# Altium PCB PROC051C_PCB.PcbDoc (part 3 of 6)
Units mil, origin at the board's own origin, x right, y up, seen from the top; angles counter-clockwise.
Board outline 3304.03 x 2647.77 mil, 6 copper layers (TOP, L2, L3, L4, L5, BOTTOM), stack 55.54 mil thick; 370 components, 273 nets, 1273 pads, 1381 vias.
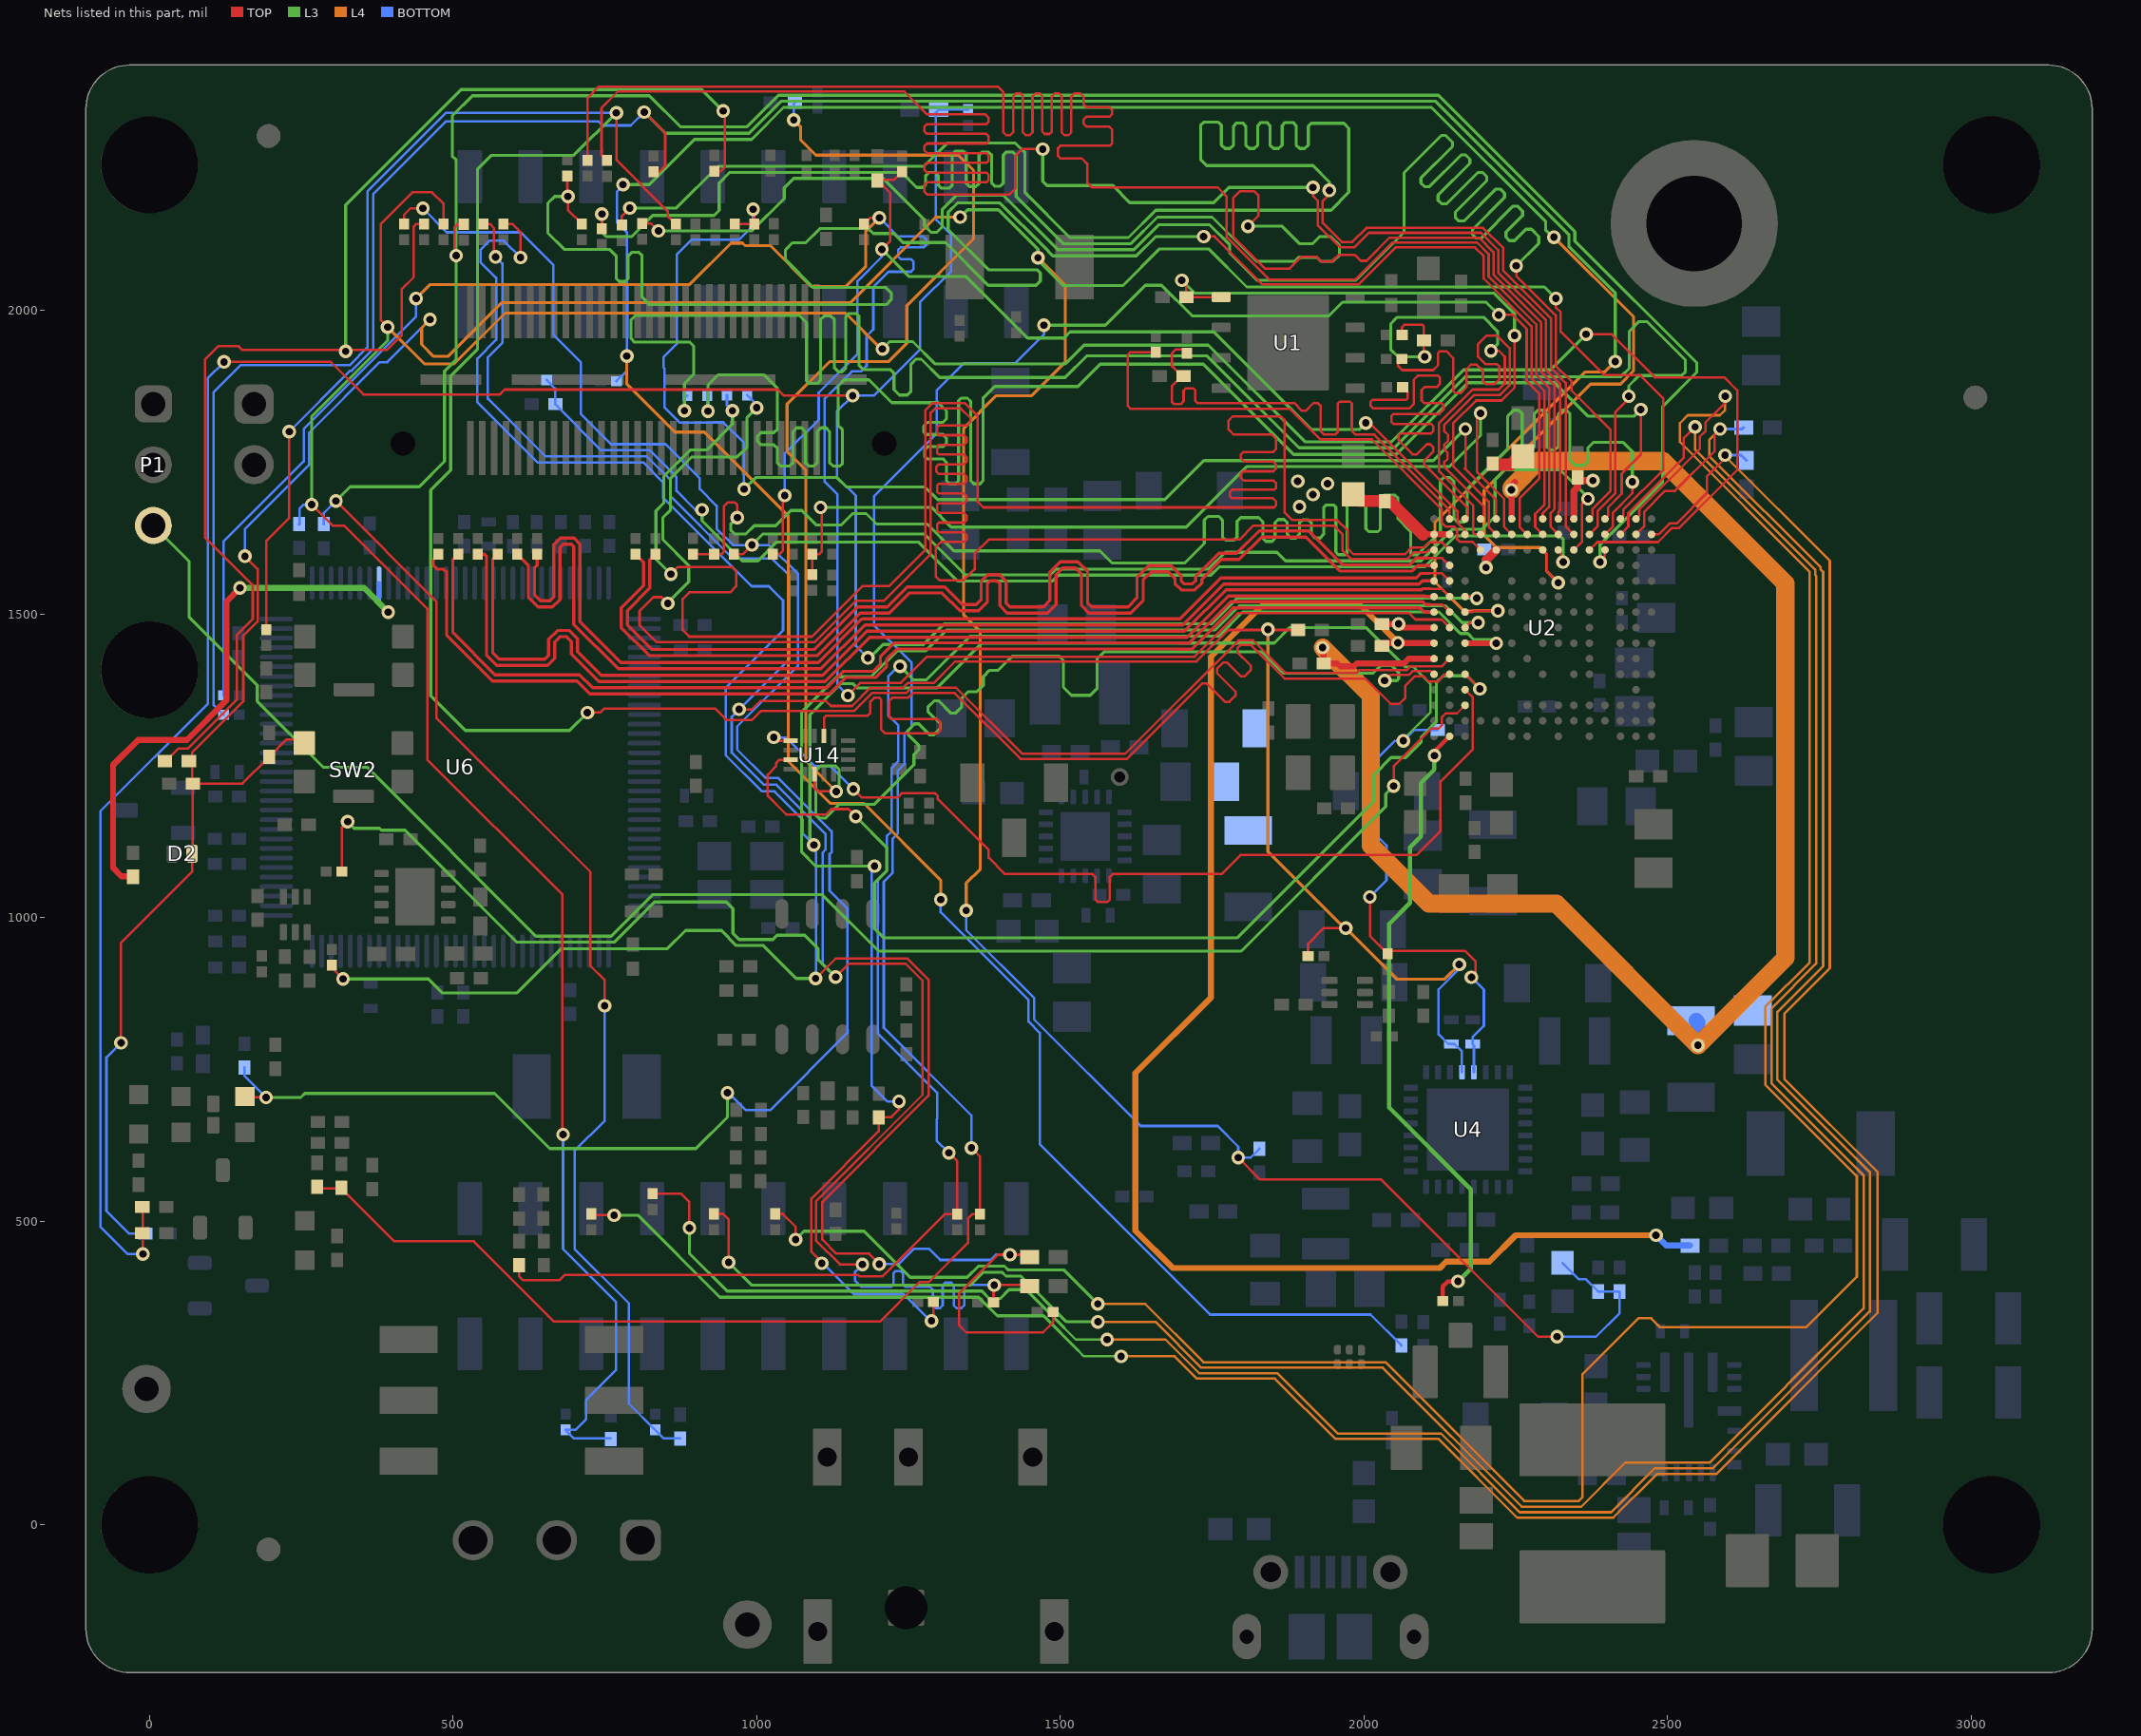
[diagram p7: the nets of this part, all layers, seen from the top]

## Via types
v1: diameter 22.4, hole 12.2, TOP to BOTTOM, tented both sides, 810 vias
v2: diameter 13.77/15.74 (per signal layer), hole 5.9, TOP to L2, tented both sides, 528 vias
v3: diameter 19.68, hole 7.87, TOP to BOTTOM, 23 vias
v4: diameter 19.68, hole 7.87, TOP to BOTTOM, tented both sides, 7 vias
v5: diameter 22.4, hole 12.1, TOP to BOTTOM, tented both sides, 7 vias
v6: diameter 16, hole 8, TOP to BOTTOM, tented both sides, 4 vias
v7: diameter 13.77/15.74 (per signal layer), hole 5.9, TOP to L2, tented top, 1 vias
v8: diameter 22.4/22.4/22.4/22.4/22.4/22.4 (per signal layer), hole 12.2, TOP to BOTTOM, tented both sides, 1 vias

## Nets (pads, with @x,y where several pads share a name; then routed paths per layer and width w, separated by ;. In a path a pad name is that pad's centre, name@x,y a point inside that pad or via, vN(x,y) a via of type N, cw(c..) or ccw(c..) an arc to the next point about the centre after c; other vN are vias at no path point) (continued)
AR_1V24: C3.2 C4.2 C6.2 C7.2 C55.1 C89.2 C101.1 C105.1 L5.2 R146.2 U2.G15 U2.H15 U2.N11 U2.P14 U2.P15 U2.R6 | length 2810.6
  TOP w10: C101.1@2029.68,1448 2033.99,1452.31 2056,1452.31 U2.G15@2115.42,1452.31 ; C4.2@2029.69,1484 v1(2057,1484) 2063.1,1477.9 U2.H15@2115.42,1477.9 ; 2097.06,1631.44 U2.P15@2115.42,1631.44 U2.P14@2141.01,1631.44
  TOP w12: U2.R6@2345.73,1657.03 2345.73,1703 2352,1709.27 C3.2@2352,1725.31 2357.31,1720 v1@2373,1720
  TOP w15: v1(2201,1577) 2201,1589.07 U2.N11@2217.78,1605.85
  TOP w20: C89.2@1993.2,1686.3 C6.2@2034.5,1686.3 ; C6.2@2034.5,1685.91 2042.59,1685.91 2097.06,1631.44
  L4 w10: v1(2056,1453) 1994.63,1514.37 1832.51,1514.37 1747.88,1429.74 1747.88,868.36 1623.8,744.27 1623.8,484.97 1623.54,484.71 1685.25,423 2125.14,423 2135.5,433.37 2206.43,433.37 2250.06,477 v1(2481,477)
  BOTTOM w10: v1(2481,477) 2498,460 R146.2@2537,460
  BOTTOM w20: v1@2200.31,1577.69 v1(2201,1577)
  other v1: 1894,1677 1916,1697 1940,1715 1891,1719 2377,1720
AR_3V3: C5.2 C80.1 C84.2 C87.2 L10.2 U2.F15 U2.R10 | length 2795.5
  TOP w10: v1(1932,1445) 1933.69,1443.31 C84.2@1933.69,1419 1956.22,1419 1961.11,1414.11 1983.23,1414.11 1988.11,1419 2066,1419 2073.72,1426.72 U2.F15@2115.42,1426.72 ; v1(2243,1704.83) 2243,1712.26 v1@2243.37,1712.63 ; U2.R10@2243.37,1657.03 2243.37,1704.83 v1@2243.37,1712.63 ; 2248.74,1718 v1@2243.37,1712.63
  TOP w20: C5.2@2211.95,1748.3 2212.14,1748.11 2213.85,1746.4 2241.8,1746.4 2255.3,1759.9 C87.2@2261.8,1759.9
  L4 w30: v1(1932,1445) 2011.46,1365.54 2011.46,1118.62 2106.95,1023.14 2316.75,1023.14 v1(2550,789.89) 2694,933.89 2694,1550.78 2492.58,1752.2 2287.2,1752.2 2243,1708 v1(2243,1704.83)
  BOTTOM w25: L10.2@2547,830.64 2550,827.64 v1(2550,789.89)
AR_ANAMUX: P1.3 U2.C13 | length 2792.8
  TOP w4: v1@2056.9,1213.47 2053.38,1217 v1(2049,1217) 2049,1249.74 2110.82,1311.56 2122.56,1311.56 2128,1317 2128,1330 2134.66,1336.66 2153.31,1336.66 U2.C13@2166.6,1349.95
  L3 w5: P1.3@6.27,1646.15 65,1587.42 65,1495.2 177.4,1382.8 177.4,1356.45 285.85,1248 358,1248 636.25,969.75 760.31,969.75 828.56,1038 1108.06,1038 1201.06,945 1797.78,945 2036.09,1183.32 2036.09,1204.09 v1(2049,1217)
AR_ANATEST1: R46.1 R104.2 U2.P1 | length 4276.8
  TOP w4: R104.2@727.75,512.27 730.02,510 v1(765,510) ; U2.P1@2473.68,1631.44 2485.69,1631.44 2504.26,1650.01 2515.81,1650.01 2564.89,1699.1 2564.89,1726.58 2594.66,1756.35 v1(2594.66,1761.9)
  L3 w4: 1529.65,286.92 1538.97,277.6 v1(1600.06,277.6)
  L3 w5: v1(765,510) 804.19,510 939.19,375 1365.46,375 1396.16,344.3 1472.27,344.3 1529.65,286.92
  L4 w4: v1(1600.06,277.6) 1688.07,277.6 1724.67,241 1853.51,241 1953.05,141.46 2122.98,141.46 2252.64,11.8 2410.65,11.8 2482.43,83.58 2580.03,83.58 2845.54,349.09 2845.54,581.49 2692.23,734.8 2692.23,842 2767.24,917.01 2767.24,1588.08 2594.66,1760.66 v1(2594.66,1761.9)
  BOTTOM w5: v1(2594.66,1761.9) 2621.34,1761.9 R46.1@2629.9,1753.34
AR_ANATEST2: R94.2 R100.1 U2.P2 | length 4338.2
  TOP w4: R94.2@828.25,545.27 875.73,545.27 889,532 v1(889,489) ; U2.P2@2448.09,1631.44 2461.38,1644.73 2461.38,1668.38 2496,1703 2512.11,1703 2577.46,1768.35 2577.46,1796.03 v1(2586.42,1805)
  L3 w4: 1506.18,324.54 1525.46,305.26 v1(1577.08,305.26)
  L3 w5: v1(889,489) v1(889,489) 889.05,447.26 951.31,385 1370.72,385 1382.72,373 1401.4,373 1415.7,387.3 1443.42,387.3 1506.18,324.54
  L4 w4: v1(1577.08,305.26) 1673.15,305.26 1728.4,250 1857.24,250 1956.77,150.46 2126.71,150.46 2256.37,20.8 2406.92,20.8 2479.57,93.45 2575.08,93.45 2833.12,351.49 2833.12,581.18 2681.1,733.21 2681.1,845 2756.22,920.12 2756.22,1569.54 2752.26,1573.5 2752.26,1577.15 2568.67,1760.73 2568.67,1787.25 v1(2586.42,1805)
  BOTTOM w5: v1@2586.42,1800.26 v1(2586.42,1805) 2622.94,1805 R100.1@2625.38,1807.44
AR_ANATEST3: R105.2 U2.P3 | length 4143.4
  TOP w4: R105.2@929.75,512.27 944.73,512.27 953.8,503.2 v1(953.8,432.4) ; U2.P3@2422.5,1631.44 2435.45,1644.39 2435.45,1666.45 2526.85,1757.85 2526.85,1790.1 v1(2545.22,1808.48)
  L3 w5: v1(953.8,432.4) 991.2,395 1352,395 1373.16,416.16 1403.84,416.16 1410.26,409.74 1435.12,409.74 1510.39,334.46 v1(1561.94,334.46)
  L4 w4: v1(1561.94,334.46) 1656.67,334.46 1732.13,259 2030.9,259 2260.1,29.8 2357.65,29.8 2430.3,102.45 2569.05,102.45 2822.84,356.24 2822.84,575.93 2671.04,727.73 2671.04,850.58 2744.82,924.36 2744.82,1563.04 2743.26,1564.6 2743.26,1573.42 2545.22,1771.46 v1(2545.22,1808.48)
AR_ANATEST4: R106.2 U2.R2 | length 4256.2
  TOP w4: R106.2@1030.25,512.27 1042.73,512.27 1064,491 v1(1064,470) ; U2.R2@2448.09,1657.03 2453.38,1662.32 2453.38,1672.38 2553.22,1772.22 2553.22,1792.16 2562.42,1801.36 2562.42,1815.6 2595,1848.18 v1(2595,1859)
  L3 w5: v1(1064,470) 1077.7,483.7 1176.44,483.7 1252.34,407.8 1346.8,407.8 1365.16,426.16 1407.98,426.16 1414.4,419.74 1506.1,419.74 v1(1561.84,364)
  L4 w4: v1(1561.84,364) 1639.86,364 1735.86,268 2035.33,268 2264.03,39.3 2353.71,39.3 2359.69,45.27 2359.69,247.95 2452.01,340.27 2473.04,340.27 2487.42,325.89 2728.8,325.89 2811.82,408.91 2811.82,574.23 2660.97,725.08 2660.97,853.24 2734.26,926.53 2734.26,1569.69 2520.35,1783.6 2520.35,1814.53 2533.5,1827.68 2586.1,1827.68 2595,1836.58 v1(2595,1859)
AR_BSS_LOGGER: R31.1 R135.1 U2.H14 | length 3794.9
  TOP w4: v1(1150,1366) 1171,1387 1237.4,1387 1280.4,1430 1721,1430 1793,1502 2074,1502 2084.81,1491.19 2127.72,1491.19 U2.H14@2141.01,1477.9 ; R31.1@1176.75,2142.71 1187.04,2153 v1(1202,2153)
  L4 w5: v1(439,2020) 462,2043 889.6,2043 958.05,2111.45 976.26,2111.45 980.71,2107 1022.36,2107 1089.36,2040 1147,2040 1179.3,2072.3 1179.3,2130.3 v1(1202,2153)
  BOTTOM w4: R135.1@121.79,1366.19 121.79,1619.69 253.86,1751.76 253.86,1805.3 439,1990.44 v1(439,2020) ; v1(1150,1366) 1133,1383 1133,1697.12 1112,1718.12 1112,1855.3 1156.7,1900 1172,1900 1181,1909 1181,1958 1192,1969 1192,2039 1217,2064 1254,2064 1258,2068 1258,2081 1254,2085 1237,2085 1233,2089 1233,2100 1237,2104 1275,2104 1279,2108 1279,2117.3 1274,2122.3 1232.7,2122.3 v1(1202,2153)
AR_CS1: R14.1 U2.E15 U14.10 | length 3311.4
  TOP w4: U14.10@1095.13,1236.5 1095.13,1213.87 1101,1208 v1(1131,1208) ; v1(2034.18,1390.7) 2043.48,1400 2073.87,1400 2079.87,1406 2110.54,1406 U2.E15@2115.42,1401.13
  L3 w5: v1(1131,1208) 1135.58,1212.58 1135.58,1244.42 1130,1250 1105,1250 1097.5,1242.5 1097.5,1169.5 1103,1164 1113,1164 1136,1187 1194,1187 1259,1252 1259,1268.91 1259.6,1269.51 1266.94,1276.85 1266.94,1283.92 1249.21,1301.65 1249.21,1308.73 1259.82,1319.33 1266.89,1319.33 1284.62,1301.6 1291.69,1301.6 1302.3,1312.21 1302.3,1319.28 1281.8,1339.78 1281.8,1346.85 1292.4,1357.46 1299.47,1357.46 1319.98,1336.95 1327.05,1336.95 1337.65,1347.56 1337.65,1354.63 1337.65,1361.7 1348.26,1372.31 1355.33,1372.31 1362.4,1372.31 1373.01,1382.92 1373.01,1389.99 1373.01,1397.06 1383.62,1407.67 1390.69,1407.67 1397.76,1407.67 1411.9,1421.81 1420.74,1430.65 1498.21,1430.65 1505,1423.86 1505,1379.86 1518.36,1366.5 1549.21,1366.5 1560.71,1378 1560.71,1427 1571.58,1437.88 1832.12,1437.88 1867.2,1402.8 2014.8,1402.8 2027.2,1415.2 2045.95,1415.2 2057.2,1403.95 2057.2,1393.45 2054.45,1390.7 v1(2034.18,1390.7)
  L4 w5: v1(1061,2314) 1072.44,2302.56 1072.44,2280.78 1097.22,2256 1332,2256 1357.16,2230.84 1357.16,2118.16 1247,2008 1247,1946.29 1216.66,1915.95 1119.95,1915.95 1050,1846 1050,1768 1081,1737 1081,1258 v1(1131,1208)
  BOTTOM w4: v1(1061,2314) 1061,2341.02 R14.1@1062.59,2342.6
AR_DMM_CLK: R54.1 U2.N15 | length 3198.6
  TOP w4: v1(853.5,1517.8) 843.3,1528 830,1528 807,1505 807,1482 835,1454 1095,1454 1163,1522 1209.31,1522 1286.62,1599.3 1286.62,1831.62 1294,1839 1336,1839 1352.04,1822.96 1352.04,1817 1345.88,1810.84 1299.73,1810.84 1296.9,1808.01 1296.9,1797.67 1299.73,1794.84 1341.35,1794.84 1346.04,1790.15 1346.04,1783.53 1341.35,1778.84 1299.73,1778.84 1296.9,1776.01 1296.9,1765.67 1299.73,1762.84 1341.35,1762.84 1346.04,1758.15 1346.04,1751.53 1341.35,1746.84 1299.73,1746.84 1295.9,1743.01 1295.9,1734.66 1299.73,1730.84 1341.35,1730.84 1346.04,1726.15 1346.04,1719.53 1341.35,1714.84 1299.73,1714.84 1296.9,1712.01 1296.9,1701.67 1299.73,1698.84 1341.35,1698.84 1346.04,1694.15 1346.04,1687.53 1341.35,1682.84 1299.73,1682.84 1297.24,1680.35 1297.24,1669.33 1299.73,1666.84 1341.35,1666.84 1346.04,1662.15 1346.04,1655.53 1341.35,1650.84 1299.73,1650.84 1296.9,1648.01 1296.9,1637.67 1299.73,1634.84 1341.35,1634.84 1346.04,1630.15 1346.04,1623.53 1341.35,1618.84 1303.16,1618.84 1294.81,1610.49 1294.81,1562.19 1301,1556 1341,1556 1359,1574 1359,1599.7 1382.3,1623 1795,1623 1818,1646 1950,1646 1965,1631 1965,1605 1979.2,1590.8 2070.96,1590.8 2082.16,1602 2103,1602 2106.85,1605.85 U2.N15@2115.42,1605.85
  L3 w5: v1(853.5,1517.8) 853.5,1518.68 888,1553.18 888,1580.1 845.3,1622.8 845.3,1659.2 858,1671.9 858,1724 893,1759 968.02,1759 984.02,1775.03 983.98,1823.96 v1(1000,1840)
  BOTTOM w4: R54.1@984,1861.01 1000,1845.01 v1(1000,1840)
AR_DMM_SYNC: R55.1 U2.N14 | length 3238.5
  TOP w4: v1(858.6,1566) 870.6,1578 959,1578 966.1,1570.9 966.1,1545.74 956.36,1536 889,1536 878,1525 878,1474 889,1463 1091,1463 1174.1,1546.1 1218.1,1546.1 1277.55,1605.55 1277.55,1835.55 1290,1848 1342,1848 1364.01,1825.99 1364.01,1684.99 1373.11,1675.89 1851.89,1675.89 1855.2,1679.2 1855.2,1685.8 1850,1691 1783,1691 1779,1695 1779,1701 1783,1705 1852.31,1705 1855.2,1707.89 1855.2,1715.8 1851,1720 1801.99,1720 1797.5,1724.49 1797.5,1731.11 1801.79,1735.4 1850.71,1735.4 1855.2,1739.89 1855.2,1746.51 1850.31,1751.4 1802.59,1751.4 1797.5,1756.49 1797.5,1763.11 1801.79,1767.4 1850.71,1767.4 1855.2,1771.89 1855.2,1788.8 1848,1796 1785,1796 1777,1804 1777,1819 1784,1826 1863,1826 1869,1820 1869,1668 1882,1655 1956,1655 1973,1638 1973,1608.31 1982.51,1598.8 2067.65,1598.8 2078.85,1610 2099,1610 2107.15,1618.15 2128.71,1618.15 U2.N14@2141.01,1605.85
  L3 w5: v1(858.6,1566) 834,1590.6 834,1670.3 846.9,1683.2 846.9,1727.2 890.2,1770.5 917.4,1770.5 960,1813.1 v1(960,1835)
  BOTTOM w4: R55.1@951,1860.81 951,1844 v1(960,1835)
AR_DP0: R56.1 U2.R4 | length 3201.8
  TOP w4: U2.R4@2396.91,1657.03 2402.2,1662.32 2402.2,1676.2 2424.48,1698.48 2424.48,1731.48 2456,1763 v1(2456,1837)
  L3 w5: v1(919.7,1834.5) 919.7,1877.6 936.1,1894 1012.1,1894 1034,1872.1 1034,1804.87 1028.14,1799.01 1006.86,1799.01 1001,1793.15 1001,1784.87 1006.86,1779.01 1028.14,1779.01 1034,1773.15 1034,1749.01 1039.01,1744 1053.99,1744 1059.85,1749.86 1059.85,1801.14 1065.71,1807 1073.99,1807 1079.85,1801.14 1079.85,1749.86 1085.71,1744 1093.99,1744 1099.85,1749.86 1099.85,1801.14 1105.71,1807 1113.99,1807 1119.85,1801.14 1119.85,1749.86 1125.71,1744 1137,1744 1141.32,1748.32 1141.32,1803.58 1134,1810.9 1134,1875.4 1144.6,1886 1185,1886 1222.46,1848.54 1298.8,1848.54 1312.54,1834.8 1312.54,1821.77 1306.68,1815.91 1281.11,1815.91 1275.12,1809.91 1275.12,1799.54 1278.75,1795.91 1306.68,1795.91 1312.54,1790.05 1312.54,1781.77 1306.68,1775.91 1281.66,1775.91 1276.79,1771.05 1276.79,1758.97 1279.85,1755.91 1306.68,1755.91 1312.54,1750.05 1312.54,1719.73 1317.54,1714.73 1327.54,1714.73 1332.54,1719.73 1332.54,1851.68 1336.67,1855.81 1346.99,1855.81 1352.54,1850.26 1352.54,1719.73 1357.54,1714.73 1367.54,1714.73 1372.54,1719.73 1372.54,1855.54 1392,1875 1529,1875 1565.7,1911.7 1735.5,1911.7 1884.2,1763 2053,1763 2171.26,1881.26 2313.74,1881.26 2368.7,1826.3 2445.3,1826.3 v1(2456,1837)
  BOTTOM w4: R56.1@918.5,1860.31 919.7,1859.11 v1(919.7,1834.5)
AR_DP1: R57.1 U2.P5 | length 3202.6
  TOP w4: U2.P5@2371.32,1631.44 2384.61,1644.73 2384.61,1669.97 2414,1699.36 2414,1833 2436.17,1855.17 v1(2436.17,1859)
  L3 w5: v1(881,1835) 881,1880 896,1895 896,1942 889.9,1948.1 798.9,1948.1 793,1954 793,1985 800.1,1992.1 1070.21,1992.1 1082,1980.31 1082,1884 1086,1880 1100,1880 1104.97,1884.97 1104.97,1985.26 1110.79,1991.08 1122.19,1991.08 1127.99,1985.28 1127.99,1905.44 1134.43,1899 1140.56,1899 1146.69,1905.13 1146.69,1990.69 1151,1995 1164,1995 1168.7,1990.3 1168.7,1909.3 1175,1903 1220,1903 1226,1897 1226,1870 1235,1861 1248,1861 1254,1867 1254,1912 1262,1920 1271,1920 1301,1890 1508,1890 1543.4,1925.4 1741.7,1925.4 1893.1,1774 2049.86,1774 2167.12,1891.26 2423.26,1891.26 2437,1905 2437,1966 2453,1982 2465.91,1982 2529.5,1918.41 2529.5,1899.5 2523,1893 2453,1893 2436.17,1876.17 v1(2436.17,1859)
  BOTTOM w4: v1(881,1835) 881,1855.11 880.7,1855.41 R57.1@885.6,1860.31
AR_DP2: R179.1 U2.R5 | length 3203.3
  TOP w4: R179.1@811,2143.49 826.01,2143.49 v1(838.1,2131.4) ; v1(2250.8,2073.7) 2250.8,2057.2 2316,1992 2316,1909 2342,1883 2342,1868 2405.89,1804.11 2405.89,1702.57 2376.61,1673.29 2376.61,1662.32 U2.R5@2371.32,1657.03
  L3 w5: v1(838.1,2131.4) 992.2,2131.4 1045.3,2184.5 1045.3,2202.16 1060.84,2217.7 1208.3,2217.7 1276,2150 1276,2140 1287,2129 1296.74,2129 1305.3,2137.56 1305.3,2166.3 1328.8,2189.8 1406.4,2189.8 1495.9,2100.3 1621.16,2100.3 1662.56,2141.7 1745.3,2141.7 1779,2108 1779,2095 1824,2050 1987,2050 2066,2129 2066,2227 2127.66,2288.66 2134.74,2288.66 2145.89,2277.51 2145.89,2270.43 2093.87,2218.41 2093.87,2210.13 2099.74,2204.26 2108.02,2204.26 2160.34,2256.58 2167.42,2256.58 2174.49,2249.51 2174.49,2242.43 2122.17,2190.11 2122.17,2181.83 2128.04,2175.96 2136.32,2175.96 2188.14,2227.78 2195.22,2227.78 2202.29,2220.71 2202.29,2213.63 2150.47,2161.81 2150.47,2153.53 2156.34,2147.66 2164.62,2147.66 2217.29,2200.33 2224.37,2200.33 2231.44,2193.26 2231.44,2186.18 2178.77,2133.51 2178.77,2125.23 2184.64,2119.36 2192.92,2119.36 2245.79,2172.23 2252.87,2172.23 2261.17,2163.93 2261.17,2156.85 2233.8,2129.48 2233.8,2121.2 2239.67,2115.33 2247.95,2115.33 2266.62,2134 2276,2134 2288,2122 2288,2110.9 v1(2250.8,2073.7)
AR_DP3: R180.1 U2.P6 | length 3247.7
  TOP w4: R180.1@777.7,2143.69 777.7,2155.7 v1(791,2169) ; v1(1943,2198) 1943,2191.31 1932,2180.31 1932,2144.31 1963.31,2113 1981,2113 2004.2,2136.2 2196.13,2136.2 2229.35,2102.98 2229.35,2065.91 2308,1987.25 2308,1905.69 2332.44,1881.25 2332.44,1644.73 U2.P6@2345.73,1631.44
  L3 w5: v1(791,2169) 867.5,2169 936.2,2237.7 1275.3,2237.7 1313.6,2276 1426,2276 1441.7,2260.3 1441.7,2194.1 1515.5,2120.3 1612.16,2120.3 1657.35,2165.49 1945.69,2165.49 1975,2194.8 1975,2300.4 1966.8,2308.6 1913.32,2308.6 1908.32,2303.6 1908.32,2272.86 1902.46,2267 1894.18,2267 1888.32,2272.86 1888.32,2304.9 1883.32,2309.9 1870.27,2309.9 1865.27,2304.9 1865.27,2272.86 1859.41,2267 1851.13,2267 1845.27,2272.86 1845.27,2304.9 1840.27,2309.9 1830.27,2309.9 1825.27,2304.9 1825.27,2272.86 1819.41,2267 1811.13,2267 1805.27,2272.86 1805.27,2304.1 1800.27,2309.1 1790.27,2309.1 1785.27,2304.1 1785.27,2272.86 1779.41,2267 1771.13,2267 1765.27,2272.86 1765.27,2305.4 1760.27,2310.4 1736,2310.4 1731,2305.4 1731,2249 1741,2239 1916,2239 1943,2212 v1(1943,2198)
AR_DP4: R181.1 U2.R7 | length 3253.6
  TOP w4: R181.1@753.5,2247.29 744.4,2256.39 744.4,2334 771.4,2361 1243,2361 1280.69,2323.31 1376.31,2323.31 1382,2317.62 1382,2311.31 1378,2307.31 1280.69,2307.31 1276,2302.62 1276,2296 1280.69,2291.31 1377.99,2291.31 1382,2287.3 1382,2279.31 1378,2275.31 1280.69,2275.31 1276,2270.62 1276,2264 1280.69,2259.31 1377.99,2259.31 1382,2255.3 1382,2247.31 1378,2243.31 1280.69,2243.31 1276,2238.62 1276,2232 1280.69,2227.31 1377.99,2227.31 1382,2223.3 1382,2215.31 1378,2211.31 1280.69,2211.31 1276,2206.62 1276,2196 1281,2191 1416,2191 1426,2201 1426,2255 1437,2266 v1(1471,2266) ; v1(1916,2203) 1916,2189 1924,2181 1924,2141 1961,2104 1984,2104 2008.2,2128.2 2192.81,2128.2 2221.35,2099.67 2221.35,2062.59 2300,1983.94 2300,1902.37 2323,1879.37 2323,1670.86 2320.14,1668 U2.R7@2320.14,1657.03
  L3 w5: v1(1471,2266) 1471,2213 1478,2206 1586.46,2206 1614.46,2178 1752.7,2178 1777.7,2203 v1(1916,2203)
AR_DP5: R182.1 U2.P7 | length 3177.1
  TOP w4: R182.1@745,2137.99 v1(745,2159) ; v1(1809,2139) 1826,2156 1826,2190 1819,2197 1796,2197 1785,2186 1785,2121.5 1837.5,2069 1877,2069 1897,2089 1921,2089 1929,2081 1948,2081 1959,2092 1985,2092 1995,2082 2004,2082 2042.2,2120.2 2189.5,2120.2 2213.35,2096.35 2213.35,2059.28 2292,1980.63 2292,1899 2314,1877 2314,1673.17 2307.6,1666.77 2307.6,1643.98 U2.P7@2320.14,1631.44
  L3 w5: v1(745,2159) 745,2129 752,2122 794,2122 828.8,2156.8 929.8,2156.8 938,2165 938,2210 955.7,2227.7 1238.24,2227.7 1263.14,2202.8 1273.14,2202.8 1278.14,2207.8 1278.14,2222.5 1283.14,2227.5 1294,2227.5 1299,2222.5 1299,2206.6 1304,2201.6 1317,2201.6 1322,2206.6 1322,2257.4 1327,2262.4 1340,2262.4 1345,2257.4 1345,2210 1350.5,2204.5 1361,2204.5 1366,2209.5 1366,2256.3 1371,2261.3 1382,2261.3 1387,2256.3 1387,2210.1 1392,2205.1 1401,2205.1 1406,2210.1 1406,2256 1411,2261 1422,2261 1427,2256 1427,2188 1504.7,2110.3 1616.3,2110.3 1660,2154 1750,2154 1822.66,2081.34 1886.34,2081.34 1893,2088 1922.34,2088 1929,2081.34 1949.05,2081.34 1959.79,2092.09 1959.79,2107.28 1945.07,2122 1927,2122 1915,2110 1894.35,2110 1865.35,2139 v1(1809,2139)
AR_DP6: R183.1 U2.R8 | length 3114.7
  TOP w4: R183.1@721,2247.69 721,2350 740,2369 1397,2369 1406.14,2359.86 1406.14,2293.69 1410.83,2289 1417.45,2289 1422.14,2293.69 1422.14,2352.81 1427.23,2357.9 1433.85,2357.9 1438.14,2353.61 1438.14,2293.69 1442.83,2289 1449.45,2289 1454.14,2293.69 1454.14,2352.81 1459.23,2357.9 1465.85,2357.9 1470.14,2353.61 1470.14,2295 1474.14,2291 1482.14,2291 1486.14,2295 1486.14,2352.81 1491.23,2357.9 1497.85,2357.9 1502.14,2353.61 1502.14,2293.69 1506.83,2289 1513.45,2289 1518.14,2293.69 1518.14,2352.81 1523.23,2357.9 1532.6,2357.9 1538,2352.5 1538,2340.1 1542.69,2335.41 1580.01,2335.41 1585.2,2330.22 1585.2,2323.6 1581.01,2319.41 1542.69,2319.41 1538,2314.72 1538,2308.1 1542.69,2303.41 1580.01,2303.41 1585.2,2298.22 1585.2,2275.2 1581.66,2271.66 1500.05,2271.66 1496.1,2267.71 1496.1,2254.73 1499.92,2250.91 1535.09,2250.91 1544.2,2241.8 1544.2,2210.8 1551.9,2203.1 1758.9,2203.1 1774,2188 1774,2121.19 1843.96,2051.23 1986.23,2051.23 2047.2,2112.2 2186.19,2112.2 2205.35,2093.04 2205.35,2055.97 2284,1977.31 2284,1894 2305,1873 2305,1676.69 2294.55,1666.24 U2.R8@2294.55,1657.03
AR_DP7: R60.2 R184.1 U2.P8 | length 3352.6
  TOP w4: R60.2@688,2222.01 688,2189 v1(689,2188) 689,2165.99 R184.1@712,2142.99 ; v1(1736,2122) 1754,2122 1832.77,2043.23 1991.23,2043.23 2052.2,2104.2 2182.87,2104.2 2197.35,2089.73 2197.35,2052.65 2276,1974 2276,1889 2297,1868 2297,1680 2282.05,1665.05 2282.05,1643.94 U2.P8@2294.55,1631.44
  L3 w5: v1(689,2188) 667,2188 656,2177 656,2128 683,2101 757.54,2101 768.4,2090.14 768.4,2053.1 773.4,2048.1 783.4,2048.1 788.4,2053.1 788.4,2090.14 794.26,2096 806,2096 811,2091 811,2022 823.1,2009.9 1213.3,2009.9 1221.6,2018.2 1221.6,2029.1 1212.7,2038 1093.14,2038 1047.3,2083.84 1047.3,2100.16 1058.84,2111.7 1080.7,2111.7 1104,2135 1184,2135 1192,2127 1226,2127 1240.9,2112.1 1310.9,2112.1 1381.2,2041.8 1460.3,2041.8 1467.1,2048.6 1467.1,2061.9 1461.7,2067.3 1381.7,2067.3 1315.3,2133.7 1315.3,2162.16 1330.54,2177.4 1400.74,2177.4 1473,2105.14 1473,2105 1487.7,2090.3 1625.3,2090.3 1657,2122 v1(1736,2122)
AR_GPIO_0: R164.1 R178.2 U2.H13 | length 2610.4
  TOP w4: v1(1107,431) 1107,433 1090,450 1090,537.32 1200.8,648.12 R178.2@1200.8,670.91 1200.8,671.7 1221.7,671.7 1234.2,684.2 v1(1234.2,697.5) ; v1(1288,336) 1290.99,338.99 R164.1@1290.99,367 ; U2.H13@2166.6,1477.9 2174.7,1486 2183,1486 2185.5,1483.5 v1@2188,1481 ; v1(2188,1486) v1@2188,1481 ; v1@2190,1479 v1@2188,1481
  L3 w5: v1(1194,1085) 1097.3,1085 1074,1108.3 1074,1339 1132,1397 1188.14,1397 1230.52,1439.38 1277.97,1439.38 1312.59,1474 1754.86,1474 1794.56,1513.7 2134.3,1513.7 2162,1486 v1(2188,1486)
  BOTTOM w4: v1(1107,431) 1109,431 1160,380 1242,380 1286,336 v1(1288,336) ; v1(1194,1085) 1189.2,1080.2 1189.2,723.2 1214.9,697.5 v1(1234.2,697.5)
AR_GPIO_1: R9.2 R72.2 U2.J13 | length 4001.2
  TOP w4: R72.2@192.5,1474.24 192.5,1620.81 230.02,1658.33 v1(230.02,1800.7) ; v1(814.6,2327.1) 849.2,2292.5 849.2,2238.2 839.73,2228.73 R9.2@829.75,2228.73 ; U2.J13@2166.6,1503.49 2178.49,1503.49 2180.45,1505.45 v1(2220.59,1505.45)
  L3 w5: v1(814.6,2327.1) 849.7,2292 987.2,2292 1039.94,2344.74 2118.36,2344.74 2337.4,2125.7 2337.4,2105.8 2414,2029.19 v1(2414,1916)
  L4 w5: v1(2220.59,1505.45) 2220.34,1505.7 2179.84,1505.7 2179.59,1505.45 2164.55,1505.45 2117,1553 2117,1651.14 2364.86,1899 2397,1899 v1(2414,1916)
  BOTTOM w4: v1(230.02,1800.7) 330.32,1901 333,1901 368.21,1936.21 368.21,2191.71 488.5,2312 739.03,2312 746.02,2305.01 792.51,2305.01 v1(814.6,2327.1)
AR_GPIO_2: R8.2 R110.2 R116.1 R147.1 U2.K13 | length 4887.2
  TOP w4: R110.2@-11.18,523.77 -11,523.59 -11,480.33 v1(-11,446) ; v1(122.7,1915.5) 298.7,1915.5 352.2,1862 577,1862 585,1870 1035,1870 1045,1860 v1(1158,1860) ; U2.K13@2166.6,1529.08 2182.87,1529.08 v1(2185.75,1526.2)
  L3 w5: v1(1183,1428) 1186,1428 1208,1450 1274.44,1450 1308.44,1484 1749,1484 1791.2,1526.2 v1(2185.75,1526.2)
  BOTTOM w4: v1(-11,446) -36,446 -81,491 -81,1175.47 95.73,1352.21 95.73,1888.53 v1(122.7,1915.5) ; v1(1183,1428) 1163,1448 1163,1695.4 1132,1726.4 1132,1834 v1(1158,1860) 1193,1860 1269,1936 1269,2014 1320,2065 1320,2125 1295,2150 1295,2326.38 R147.1@1299.62,2331 R8.2@1348,2330.99
AR_HOSTINTR1: R10.2 R13.2 R64.2 U2.P13 | length 1945.7
  TOP w4: R64.2@1026.61,1598.73 1037.03,1598.73 1043,1604.7 1043,1692.5 v1(1046,1695.5) ; v1(1206,2101) 1220,2115 1220,2193.55 1198.79,2214.76 1198.4,2215.15 1225.67,2215.15 R10.2@1239.25,2228.73 ; v1(2003,1815) 2008.81,1815 2153.85,1669.96 2153.85,1650.79 2166.6,1638.04 U2.P13@2166.6,1631.44
  L3 w5: v1(1206,2101) 1251,2056 1336.8,2056 1336.9,2056.1 1345.1,2056.1 1446.2,1955 1506,1955 1516,1965 1752.8,1965 1913.8,1804 1992,1804 v1(2003,1815)
  BOTTOM w4: v1(1046,1695.5) 1046,1764 1102,1820 1102,1864.86 1166,1928.86 1166,2048.7 1206,2088.7 v1(1206,2101)
AR_LVDS_0_N: R48.2 U2.J15 | length 1887.4
  TOP w5.2: R48.2@475.61,1598.73 467.4,1590.52 467.4,1580.4 473.7,1574.1 484.1,1574.1 489.3,1568.9 489.3,1465.28 564.58,1390 703.96,1390 725.16,1368.8 725.33,1368.63 1119.94,1368.63 1147.13,1395.82 1196.32,1395.82 1213.8,1413.31 1213.8,1425.8 1230.6,1442.6 1691.54,1442.6 1691.74,1442.4 1716.26,1442.4 1716.86,1443 1717.3,1443 1784.9,1510.6 2092.48,1510.6 2099.59,1503.49 U2.J15@2115.42,1503.49
AR_LVDS_0_P: R49.2 U2.J14 | length 1888.2
  TOP w4: 2108,1515.99 2128.51,1515.99 U2.J14@2141.01,1503.49
  TOP w5.2: R49.2@508.25,1598.73 499.5,1589.98 499.5,1469.5 568.8,1400.2 708.19,1400.2 729.56,1378.83 1115.71,1378.83 1142.9,1406.02 1192.09,1406.02 1203.6,1417.53 1203.6,1430.02 1206.59,1433.01 ; 1204.6,1431.02 1206.59,1433.01 ; 2108,1515.99 2101.51,1515.99 2096.7,1520.8 1780.67,1520.8 1713.07,1453.2 1712.64,1453.2 1712.04,1452.6 1695.96,1452.6 1695.76,1452.8 1226.38,1452.8 1206.59,1433.01
AR_LVDS_1_N: R50.2 U2.K15 | length 1882.7
  TOP w5.2: R50.2@540.75,1598.73 551.27,1598.73 555.05,1594.95 554.91,1594.81 554.91,1432.67 571.78,1415.8 655.22,1415.8 667.2,1427.78 667.2,1454.2 676,1463 687,1463 694.8,1455.2 694.8,1434.17 739.97,1389 1112.87,1389 1185.87,1462 1699.58,1462 1699.78,1461.8 1708.22,1461.8 1708.82,1462.4 1709.26,1462.4 1776.86,1530 2100.51,1530 2101.43,1529.08 U2.K15@2115.42,1529.08
AR_LVDS_1_P: R51.2 U2.K14 | length 1888.3
  TOP w4: 2108,1542 2128.09,1542 U2.K14@2141.01,1529.08
  TOP w5.2: R51.2@573.25,1598.73 565.11,1590.59 565.11,1436.89 576,1426 651,1426 657,1432 657,1458.42 671.78,1473.2 691.22,1473.2 705,1459.42 705,1438.4 744.2,1399.2 1108.65,1399.2 1181.65,1472.2 1703.8,1472.2 1704,1472 1704.6,1472.6 1705.04,1472.6 1772.64,1540.2 2094.44,1540.2 2096.24,1542 2108,1542
AR_LVDS_CLK_N: R52.2 U2.L15 | length 1889.6
  TOP w5.2: R52.2@605.75,1598.73 623.8,1580.68 623.8,1527.88 628.1,1523.58 ; 628.1,1523.57 639.87,1511.8 663.73,1511.8 676,1524.07 676,1610 681,1615 695,1615 698.8,1611.2 698.8,1483.2 772,1410 1105.56,1410 1177.36,1481.8 1178.24,1481.8 1178.44,1482 1701.42,1482 1768.82,1549.4 2090.62,1549.4 2096.02,1554.8 2115.29,1554.8 U2.L15@2115.42,1554.67
AR_LVDS_CLK_P: R53.2 U2.L14 | length 1898.6
  TOP w4: 2108,1567.2 2128.48,1567.2 U2.L14@2141.01,1554.67
  TOP w5.2: R53.2@638.25,1598.73 638.25,1580.75 634,1576.5 634,1532.1 644.1,1522 659.5,1522 665.8,1528.3 665.8,1614.22 676.78,1625.2 699.22,1625.2 709,1615.42 709,1487.43 776.23,1420.2 1101.34,1420.2 1173.14,1492 1174.01,1492 1174.21,1492.2 1697.2,1492.2 1764.6,1559.6 2086.4,1559.6 2094,1567.2 2108,1567.2
AR_LVDS_FRCLK_N: R58.2 U2.M15 | length 1888.9
  TOP w5.2: R58.2@800.55,1598.73 813.81,1585.47 813.81,1547.24 776.8,1510.22 776.8,1477.78 822.78,1431.8 1099.93,1431.8 1169.33,1501.2 1170.2,1501.2 1171,1502 1218,1502 1251,1535 1305.01,1535 1334.45,1505.56 1365.57,1505.56 1379.76,1519.75 1379.76,1550 1384.96,1555.2 1395.36,1555.2 1400.56,1550 1400.56,1514.06 1412.62,1502 1479,1502 1493,1516 1493,1565 1504,1576 1525,1576 1534.8,1566.2 1534.8,1514.2 1547,1502 1615.91,1502 1636.4,1522.49 1636.4,1556.4 1649.8,1569.8 1677.87,1569.8 1688.88,1558.79 1688.88,1550.25 1699.33,1539.8 1721.73,1539.8 1732.9,1550.97 1732.9,1557.69 1765.21,1590 1794.42,1590 1831.62,1627.2 1904.8,1627.2 1961,1571 2079,1571 2088.26,1580.26 U2.M15@2115.42,1580.26
AR_LVDS_FRCLK_P: R59.2 U2.M14 | length 1900.3
  TOP w4: 2106,1592.8 2128.1,1592.8 2140.64,1580.26 U2.M14@2141.01,1580.26
  TOP w5.2: R59.2@833.05,1598.73 824.01,1589.69 824.01,1543.01 787,1506 787,1482 827,1442 1095.7,1442 1165.1,1511.4 1165.98,1511.4 1166.78,1512.2 1215.19,1512.2 1247.99,1545 1309.44,1545 1338.68,1515.76 1361.34,1515.76 1369.56,1523.98 1369.56,1554.23 1380.73,1565.4 1399.59,1565.4 1410.76,1554.23 1410.76,1518.29 1416.85,1512.2 1472.2,1512.2 1482.8,1522.8 1482.8,1569.22 1499.78,1586.2 1529.22,1586.2 1545,1570.42 1545,1518.42 1551.22,1512.2 1611.68,1512.2 1626.2,1526.72 1626.2,1560.62 1645.58,1580 1682.1,1580 1699.08,1563.02 1699.08,1554.48 1703.56,1550 1717.5,1550 1722.7,1555.2 1722.7,1561.92 1734.78,1574 1760.99,1600.2 1790.2,1600.2 1827.4,1637.4 1909.02,1637.4 1965.22,1581.2 2074.78,1581.2 2086.38,1592.8 2106,1592.8
AR_MCUCLKOUT: R25.1 R148.2 U2.N8 | length 5309.8
  TOP w4: U2.N8@2294.55,1605.85 2301,1599.4 2301,1571 v1(2320,1552)
  L3 w5: v1(779.81,2207.54) 821.66,2207.54 822.2,2207 897.1,2281.9 951.68,2281.9 951.78,2282 991.34,2282 994.75,2285.41 994.81,2285.41 1044.11,2334.71 2111.29,2334.71 2299.5,2146.5 2299.5,2132.5 2311,2121 v1(2313,2121)
  L4 w5: v1(786,1925) 786,1879 865,1800 913.64,1800 1052,1661.64 1052,1257.17 1120.87,1188.3 1176.48,1188.3 1303,1061.78 v1(1303,1030) ; v1(2313,2121) 2444.06,1989.94 2444.06,1900.66 2422.4,1879 2373.14,1879 2198,1703.86 2198,1630 2218.3,1609.7 2290.18,1609.7 2300.7,1599.18 2300.7,1571.3 v1(2320,1552)
  BOTTOM w4: R25.1@768.79,1883.8 785.8,1900.81 785.8,1924.8 v1(786,1925) 786,2129 770,2145 770,2196 779.81,2205.81 v1(779.81,2207.54) ; v1(1303,1030) 1303,1009.03 1447.7,864.33 1447.7,828.95 1466,810.65 1466,627 1746.61,346.39 2010.93,346.39 R148.2@2062,295.31
AR_MISO1: U2.E14 U14.2 | length 1723.2
  TOP w4: U14.2@1110.87,1299.5 1110.87,1328.87 1114.8,1332.8 1182.8,1332.8 1187,1337 1187,1356 1193.2,1362.2 1201.8,1362.2 1205,1359 1205,1310 1211,1304 1298,1304 1302,1308 1302,1322 1297,1327 1222,1327 1218,1331 1218,1357 1223.2,1362.2 1249.23,1362.2 1257.23,1370.2 1325.85,1370.2 1434.25,1261.8 1609.64,1261.8 1731.64,1383.79 1734.05,1386.21 1740.84,1386.21 1771.39,1355.66 1778.18,1355.66 1788.36,1365.84 1788.36,1372.63 1757.81,1403.18 1757.81,1409.97 1767.99,1420.15 1774.78,1420.15 1797,1397.93 1803.79,1397.93 1813.97,1408.12 1813.97,1414.9 1791.75,1437.12 1791.75,1443.91 1796.84,1449 1814.31,1449 1869.51,1393.8 2002.41,1393.8 2043.88,1352.33 2058.12,1352.33 2068.2,1362.41 2068.2,1382.2 2084,1398 2098,1398 2107.17,1388.83 2120.83,1388.83 2133.13,1401.13 U2.E14@2141.01,1401.13
AR_MOSI1: U2.D13 U14.5 | length 1621
  TOP w4: v1(1028,1297) 1026.85,1297 1021.47,1291.62 1028,1291.62 U14.5@1055.76,1291.62 ; v1(1159,1212) 1173,1198 1231.79,1198 1238.83,1205.05 1293.75,1205.05 1298.27,1200.53 1298.27,1195.2 1382,1111.46 1382,1099 1409,1072 1497.23,1072 1552.69,1072 1557.49,1067.2 1557.49,1030.64 1562.29,1025.84 1576.69,1025.84 1581.49,1030.64 1581.49,1067.2 1586.29,1072 1593.49,1072 1765.5,1072 1796.9,1103.4 2086.3,1103.4 2125.97,1143.07 2125.97,1224.44 2179.46,1277.92 2179.46,1292.8 ; U2.D13@2166.6,1375.54 2179.48,1362.65 2179.48,1292.82
  BOTTOM w4: v1(1028,1297) 1048,1297 1095,1250 1121,1250 v1(1159,1212)
AR_MSS_LOGGER: R26.1 R136.1 U2.F14 | length 4833.5
  TOP w4: v1(721.1,1337.9) 742.2,1337.9 748.5,1344.2 932,1344.2 950.15,1326.05 992.25,1326.05 1007,1340.8 1160.49,1340.8 1189.89,1370.2 1245.91,1370.2 1254.55,1378.83 1328.53,1378.83 1437.56,1269.8 1606.33,1269.8 1793.53,1457 1817.63,1457 1871.51,1403.11 1987.78,1403.11 1992.67,1408 2070.56,1408 2076.56,1414 2127.6,1414 2140.32,1426.72 U2.F14@2141.01,1426.72 ; v1(768.8,2325.9) 768.8,2248.41 853.47,2163.75 853.47,2155.82 R26.1@866.7,2142.59
  L3 w5: v1(721.1,1337.9) 691.6,1308.4 520.1,1308.4 462.9,1365.6 462.9,1704.3 495.9,1737.3 495.9,1892.3 539.9,1936.3 539.9,2232.6 563.2,2255.9 698.8,2255.9 v1(768.8,2325.9)
  BOTTOM w4: R136.1@121.79,1334.29 105.73,1350.35 105.73,1865.93 149.8,1910 329.27,1910 358.78,1939.51 358.78,2196.42 488.26,2325.9 v1(768.8,2325.9)
AR_NERR_OUT: DS1.2 R19.1 R63.2 R91.1 U2.N6 | length 4864.2
  TOP w4: DS1.2@157,704.54 191.46,704.54 v1(192,704) ; R19.1@419.25,2142.71 419.25,2157.75 430,2168.5 v1(450,2168.5) ; R63.2@962.11,1598.73 976.73,1598.73 v1(992,1614) ; U2.N6@2345.73,1605.85 2358.8,1618.92 2358.8,1682.2 2367.8,1691.2 2369,1692.4 v1(2369,1690)
  L3 w5: v1(192,704) 249,704 255.7,710.7 568.3,710.7 659,620 900,620 951.7,671.7 v1(951.7,711.59) ; v1(992,1614) 1010,1632 1276.1,1632 1343.35,1564.75 1483.52,1564.75 1493.05,1574.28 1744.14,1574.28 1771.86,1602 1857,1602 1871,1588 2094,1588 2146,1640 2195,1640 2216,1661 2216,1721.86 2231.84,1737.7 2323.3,1737.7 2369,1692 v1(2369,1690)
  BOTTOM w4: R91.1@156,753.32 156,740 v1(192,704) ; v1(450,2168.5) 489.5,2129 611,2129 665,2075 665,1960 710,1915 710,1830 760,1780 850.01,1780 906.2,1723.81 906.2,1706.2 933.99,1678.41 933.99,1641.01 961,1614 v1(992,1614) 1020,1614 1068,1566 1068,1415.22 967.8,1315.02 967.8,1277.05 1014.85,1230 1035.57,1230 1123.2,1142.37 1123.2,1107.91 1120,1104.7 1120,1044.69 1149.2,1015.49 1149.2,810.2 1022,683 982,683 953.41,711.59 v1(951.7,711.59)
AR_NERRIN: R16.1 R24.1 U2.N7 | length 1975.8
  TOP w4: U2.N7@2320.14,1605.85 2325,1600.99 2325,1586 2325,1583 v1(2328,1586)
  L3 w5: v1(910,1672) 910,1654 976,1588 1002,1588 1033,1619 1266.1,1619 1330.35,1554.75 1487.66,1554.75 1497.19,1564.28 1748.28,1564.28 1762,1578 2100,1578 2151,1629 2323,1629 2328,1624 v1(2328,1586)
  BOTTOM w4: R24.1@654.09,1885.6 667.9,1871.79 667.9,1846 668.29,1845.61 743.9,1770 824.01,1770 867.8,1726.21 867.8,1703.1 898.9,1672 v1(910,1672)
AR_NRST: C11.2 C94.2 D2.2@69.97,1105.47 R74.1 R77.2 R143.1 R144.1 R159.1 R160.1 SW2.4 U2.R3 | length 7493.4
  TOP w4: v1(-47,794) -47,959 69.97,1075.97 D2.2@69.97,1105.47 71.34,1106.83 R74.1@71.34,1221.14 ; v1(157,1595.5) 178,1574.5 178,1488 154.3,1464.3 154.3,1356.45 70.55,1272.7 70.55,1258 70.55,1221.14 R74.1@71.34,1221.14 ; SW2.4@254.99,1293.4 225.1,1293.4 197.11,1265.41 152.84,1221.14 R74.1@71.34,1221.14 ; v1(1793,605) 1829.22,568.78 2028.22,568.78 2287,310 v1(2318,310) ; v1(2316,2020) 2316,2005.68 2324,1997.68 2324,1965.31 2395.31,1894 2454,1894 2493,1855 2493,1738 2427,1672 2427,1661.53 U2.R3@2422.5,1657.03
  L3 w5: v1(1335,2154) 1347,2166 1398,2166 1463,2101 v1(1463,2087) 1463,2083 1504.7,2041.3 1603.16,2041.3 1663.56,2101.7 1744.3,2101.7 1807,2039 2297,2039 v1(2316,2020)
  L4 w5: v1(462,1985.5) 448.2,1971.7 448.2,1944.3 468,1924.5 491.3,1924.5 579.8,2013 1154,2013 1295,2154 v1(1335,2154) ; v1(1345,1012) 1345,1057 1368.2,1080.2 1368.2,1471.12 1340.87,1498.44 1340.87,1806.39 1394.48,1860 1452.71,1860 1508.2,1915.49 1508.2,2041.8 v1(1463,2087)
  BOTTOM w4: v1(-47,794) -71,770 -71,517 -34,480 R160.1@-6.68,480 ; v1(157,1595.5) 157,1640 262.97,1745.97 262.97,1799.13 378.85,1915 391.5,1915 v1(462,1985.5) ; v1(1345,1012) 1345,979.76 1456.7,868.06 1456.7,832.68 1632.38,657 1759,657 1793,623 v1(1793,605) 1813.32,605 R144.1@1828,619.68 ; v1(2318,310) 2382,310 2421,349 R143.1@2421,384.32 R159.1@2386,384.32 2365.32,405 2353.5,405 C94.2@2327,431.5
AR_NRST_MCU: R2.2 R20.1 R77.1 | length 2384.1
  TOP w4: R77.1@25.32,1258 27,1258 47.8,1278.8 63.3,1278.8 143.9,1359.4 143.9,1465.9 170,1492 170,1547.83 91,1626.83 91,1919.2 113.2,1941.4 146.6,1941.4 153,1935 323,1935 391,1935 415,1959 415,2035 435,2055 435,2138.45 439.26,2142.71 R20.1@452.11,2142.71 ; R2.2@930.05,2229.73 940.73,2229.73 947.4,2236.4 947.4,2326.1 v1(944.6,2328.9)
  L3 w5: v1@323,1935 323,2174.1 513,2364.1 909.4,2364.1 v1(944.6,2328.9)
  other v1: 323,1933
AR_NRST_XDS: R80.1 U6.40 | length 947.4
  TOP w10: R80.1@-27.26,1068.25 -46.14,1068.25 -60,1082.11 -60,1251.8 -18.7,1293.1 61.5,1293.1 126.6,1358.2 126.6,1520.8 v1(148.9,1543.1)
  L3 w10: v1(148.9,1543.1) 353.41,1543.1 v1(393,1503.5)
  BOTTOM w7: U6.40@377.93,1551.19 377.93,1518.57 v1(393,1503.5)
AR_OSC_CLKOUT: R111.1 U2.A14 | length 1055.5
  TOP w7.08: v1(2116.08,1267.08) 2116.08,1273.84 U2.A14@2141.01,1298.77 ; R111.1@2130.01,369 2130.01,393.01 2138,401 v1(2155,401)
  L3 w7.08: v1(2116.08,1267.08) 2116.08,1244.08 2094,1222 2094,1134 2075.9,1115.9 2075.9,1024.4 2041.74,990.24 2041.74,686.94 2176,552.68 2176,422 v1(2155,401)
AR_PMIC_CLKOUT_SOP2: R97.1 R98.1 R109.2 U2.P9 | length 4247
  TOP w4: R97.1@285,554.25 315.75,554.25 403,467 534,467 666.2,334.8 1202.8,334.8 1268,400 1283.32,400 1347.8,464.48 1347.8,504.3 1355.57,512.07 R109.2@1367.85,512.07 1367.85,606.55 v1(1353.55,620.85) ; v1(2222,1993) 2245,1993 2268,1970 2268,1884 2289,1863 2289,1723.32 2256.46,1690.78 2256.46,1643.94 U2.P9@2268.96,1631.44
  L3 w5: v1(1473,1976) 1574,1976 1639.7,2041.7 1666.9,2041.7 1717.36,1991.24 1942.24,1991.24 1965,2014 2201,2014 v1(2222,1993)
  BOTTOM w4: 1243.3,1431.7 1193,1482 1193,1694.14 1296.2,1797.34 1296.2,1868.34 1329.86,1902 1340.98,1913 1425.15,1913 1473,1960.85 v1(1473,1976) ; 1243.33,1431.7 1255.2,1419.83 1255.2,1315.2 1243.2,1303.2 1243.2,1253 1232.2,1242 1232.2,1138.34 1224,1130.14 1224,1074 1209.2,1059.2 1209.2,818.8 1353.55,674.45 v1(1353.55,620.85)
AR_QSPI_CS: R38.1 U1.1 U2.P11 | length 1116.7
  TOP w4: v1(1700,2050) 1707.49,2042.51 R38.1@1707.49,2022.18 ; R38.1@1707.49,2021.84 R38.1@1707.49,2022.18 ; U1.1@1762.93,2022.18 R38.1@1707.49,2022.18 ; U2.P11@2217.78,1631.44 2205.48,1643.74 2205.48,1685.52 2147,1744 2147,1814.32 2184.68,1852 2226.63,1852 2248,1873.37 v1(2248,1959)
  L3 w5: v1(1700,2050) 1721,2029 2213.86,2029 2248,1994.86 v1(2248,1959)
AR_QSPI_D0: R45.2 U2.R13 | length 841.4
  TOP w4: R45.2@2063.67,1873.85 2072,1865.52 2072,1856 2069,1853 2014,1853 2011,1850 2011,1843 2015,1839 2075,1839 2082,1846 2082,1886 2089,1893 2122,1893 2125,1890 2125,1879 2120,1874 2100,1874 2095,1869 2095,1852 2099,1848 2127,1848 2131,1844 2131,1837 2124,1830 2049,1830 2045,1826 2045,1817 2048.7,1813.3 2110.4,1813.3 2114.4,1809.3 2114.4,1801.7 2110.4,1797.7 2061.1,1797.7 2057.1,1793.7 2057.1,1786.4 2080.1,1763.4 2087.06,1763.4 2103.66,1780 2109,1780 2114,1775 2114,1767.7 2099.47,1753.17 2099.47,1746.53 2171,1675 2171,1661.43 U2.R13@2166.6,1657.03
AR_QSPI_D1: R39.1 U2.N12 | length 833.4
  TOP w4: R39.1@1656.9,1931.51 1615.51,1931.51 1611,1927 1611,1843 1616,1838 1878.18,1838 1928.43,1787.75 2013.25,1787.75 2128,1673 2128,1651 2134.5,1644.5 2148.5,1644.5 2153.6,1639.4 2153.6,1623.4 2158.1,1618.9 2179.14,1618.9 U2.N12@2192.19,1605.85
AR_QSPI_D2: R42.1 R43.1 U2.R14 | length 847.6
  TOP w4: R43.1@1702.89,1892 R43.1@1700,1892 ; R42.1@1708.5,1929.81 1702.31,1936 1690,1936 1684,1930 1684,1908 R43.1@1700,1892 ; U2.R14@2141.01,1657.03 2141.01,1671.49 2016.75,1795.75 1986.25,1795.75 1980,1802 1980,1847 1977,1850 1960,1850 1957,1847 1957,1800 1952.75,1795.75 1934.25,1795.75 1928.5,1801.5 1928.5,1843.5 1924,1848 1917,1848 1904,1835 1898,1835 1885,1848 1726,1848 1722,1852 1722,1869 1719,1872 1707,1872 1703,1868 1703,1851 1698,1846 1687.27,1846 1683.5,1849.77 1683.5,1875.5 R43.1@1700,1892
AR_QSPI_D3: R40.2 R41.1 U2.P12 | length 860.6
  TOP w4: R40.2@2062.67,1954.85 2062.67,1960 2062.67,1972.67 2067,1977 2096,1977 2098.86,1974.14 R41.1@2098.86,1950.98 2098.86,1925.14 v1(2100,1924) ; U2.P12@2192.19,1631.44 2182.56,1631.44 2179.6,1634.4 2179.6,1679.4 2123.9,1735.1 2123.9,1814.9 2179,1870 2222,1870 2232,1880 2232,1924 2222.3,1933.7 v1(2209.3,1933.7)
  L3 w5: v1(2100,1924) 2056,1924 2044,1936 2044,1978 2055,1989 2197,1989 2220,1966 2220,1944.4 v1(2209.3,1933.7)
AR_QSPI_SCLK: R44.2 U2.R12 | length 872.9
  TOP w4: R44.2@2062.67,1920.35 2056,1913.68 2056,1909 2063,1902 2114,1902 2122,1910 2122,1930 2125,1933 2136,1933 2147,1922 2147,1868 2151,1864 2159,1864 2169,1874 2169,1904 2176,1911 2186,1911 2196,1901 2196,1884 2201,1879 2215,1879 2223,1887 2223,1908 2219,1912 2200,1912 2188,1924 2188,1945 2202,1959 2219,1959 2240,1938 2240,1876.69 2224.31,1861 2182,1861 2132,1811 2132,1802 2138.8,1795.2 2138.8,1785.8 2132,1779 2132,1772 2138,1766 2138,1756 2132,1750 2132,1743 2197.48,1677.52 2197.48,1662.32 U2.R12@2192.19,1657.03
AR_RS232RX: R33.1 R129.1 R166.1 R172.1 U2.N4 | length 5452.4
  TOP w4: v1(307,1686.5) 472.4,1521.1 472.4,1329.2 726,1075.6 726,921 749.5,897.5 v1(749.5,855) ; v1(505,2090.5) 502,2093.5 502,2137.13 507.14,2142.27 R33.1@517.39,2142.27 ; v1(2389,1586) 2389,1591.94 2390.97,1589.97 2396.91,1595.91 U2.N4@2396.91,1605.85
  L3 w5: v1(307,1686.5) 330.4,1709.9 444.04,1709.9 485.88,1751.74 485.88,1900.28 505,1919.4 v1(505,2090.5) 505,2248.1 498.5,2254.6 498.5,2320.7 531.9,2354.1 823.1,2354.1 874.3,2302.9 983.9,2302.9 1035.74,2354.74 2122.51,2354.74 2347.4,2129.85 2347.4,2114.65 2547.53,1914.52 2548.1,1914.52 2548.1,1898.5 2492,1842.4 2492,1717.76 2389,1614.76 v1(2389,1586)
  BOTTOM w4: R129.1@287,1648.18 287,1666.5 v1(307,1686.5) ; v1(749.5,855) 749.5,665.5 700,616 700,454.39 789.4,364.99 789.4,199.64 R166.1@832.75,156.29 846.79,142.25 870.18,142.25 870.24,142.32 R172.1@874,142.32
AR_RS232TX: R21.1 R128.1 R169.1 R173.1 U2.N5 | length 5547.9
  TOP w4: v1(267,1680.5) 301.5,1646 320.4,1646 457.5,1508.9 457.5,1260.6 680,1038.1 680,644 v1(681,643) ; v1(392,1973) 380.94,1984.06 380.94,2142.93 433.01,2195 465,2195 484.35,2175.65 R21.1@484.35,2142.71 ; v1(2366,1961) 2408,1961 2479,1890 2593.59,1890 2615,1868.59 2615,1737.68 2519.34,1642.01 2507.57,1642.01 2484.36,1618.8 2384.27,1618.8 U2.N5@2371.32,1605.85
  L3 w5: v1(267,1680.5) 267,1825.5 392,1950.5 v1(392,1973) ; v1(1207,1937) 1219,1949 1256.9,1949 1293.6,1912.3 1508.3,1912.3 1539,1943 1743.7,1943 1902.7,1784 2045.72,1784 2164.02,1902.3 2307.3,1902.3 v1(2366,1961)
  L4 w5: v1(392,1973) 452.8,1912.2 501.7,1912.2 585.5,1996 1146,1996 1205,1937 v1(1207,1937)
  BOTTOM w4: R128.1@246.5,1647.75 246.89,1648.14 246.89,1648.53 246.89,1673.54 253.86,1680.5 v1(267,1680.5) ; v1(681,643) 681,454.5 768.5,367 768.5,255.49 719,205.99 719,174.3 700.99,156.29 R169.1@685.13,156.29 699.17,142.25 R173.1@759.88,142.25
AR_SCL: R5.1 R22.1 R47.2 R132.1 R163.1 R171.1 R198.1 U4.20 | length 6178.1
  TOP w4: R198.1@316.59,1075.8 316.59,1148.39 v1(326.3,1158.1) ; R22.1@550.11,2142.71 560.36,2142.71 567.1,2135.97 567.1,2091.4 v1(570,2088.5) ; v1(971,1343.25) 992.03,1343.25 1005.78,1357 1114,1357 1122.2,1348.8 1157.12,1348.8 1186.52,1378.2 1240.66,1378.2 1249.46,1387 1291.94,1387 1326.94,1422 1724.37,1422 1776.37,1474 1842,1474 R47.2@1887.31,1474 ; v1(1130,902.5) 1151.6,924.1 1245.59,924.1 1273,896.69 1273,708.32 1098,533.32 1098,468 1137,429 v1(1174,429) ; R163.1@1389.99,366 1389.99,393.99 v1(1391,395) 1445.38,395 1446.38,396 R171.1@1449.38,399 ; R5.1@1908.01,937 1908.01,957.01 1934,983 v1(1970,983)
  L3 w5: v1(326.3,1158.1) 337.2,1147.2 378.94,1147.2 381.95,1144.19 420.71,1144.19 605.15,959.75 765.2,959.75 831.45,1026 950,1026 960.69,1015.31 960.69,974.27 970.66,964.3 1026.74,964.3 1033.64,971.2 1078.8,971.2 1101,949 1101,931.5 v1(1130,902.5)
  L4 w5: v1(1842,1475) 1842,1109 1968,983 v1(1970,983) 2054,899 2133,899 v1(2157,923)
  BOTTOM w4: v1(570,2088.5) 581,2077.5 581,1947 557,1923 557,1855 652,1760 819,1760 857.8,1721.2 857.8,1694.53 960.73,1591.6 1025.39,1591.6 1054,1562.99 1054,1426.26 v1(971,1343.25) 958.8,1331.06 958.8,1271.91 1011.7,1219 1032.43,1219 1113.2,1138.23 1113.2,1112.05 1108.8,1107.65 1108.8,923.7 v1(1130,902.5) ; v1(1174,429) 1162,417 1162,402.2 1172.2,392 1220.99,392 1225,396.01 1225,414.2 1229,418.2 1236.79,418.2 1241,413.99 1241,396 1245,392 1285.5,392 1290.19,387.31 1290.19,361.59 1294.88,356.9 1301.5,356.9 1306.19,361.59 1306.19,394.9 1310.19,398.9 1320.57,398.9 1324.57,394.9 1324.57,361.59 1329.26,356.9 1336.9,356.9 1342,362 1342,390 1347,395 v1(1391,395) ; v1(2157,923) 2157,916 2123,882 2123,808 2139,792 R132.1@2144,792 2149,792 2161.43,779.57 U4.20@2161.43,745.76
AR_SDA: R23.1 R81.2 R131.1 R162.1 R168.2 R170.1 R199.2 U4.21 | length 6463.9
  TOP w4: R199.2@300.3,921.81 300.3,917.6 v1(318.8,899.1) ; R23.1@582.61,2142.71 597.29,2142.71 611,2129 v1(611,2087.5) ; v1(1097,900) 1129.8,932.8 1248.2,932.8 1283,898 1283,707 1108,532 1108,469.79 1130.99,446.8 1185.2,446.8 1201.8,430.2 v1(1201.8,429.54) ; R170.1@1449.38,441 R170.1@1453,441 ; R170.1@1449.38,445 v1(1417,445) 1397,445 1333,381 1333,329 1345,317 1471.59,317 1487.99,333.4 R162.1@1487.99,351 ; v1(2009.8,1034.28) 2009.8,970.19 R168.2@2039,940.99 2043.11,945.11 2166.89,945.11 2184,928 2184,909 v1(2177,902)
  L3 w4: v1(2064.86,1291.46) 2064.86,1293.86 2109.69,1338.69 2109.69,1385.05 2081.6,1413.14 2068,1413.14
  L3 w5: v1(318.8,899.1) 459.04,899.1 481.84,876.3 605.3,876.3 678.1,949.1 852.96,949.1 882.86,979 941.82,979 966.52,954.3 1010.7,954.3 1065,900 v1(1097,900) ; v1(1094,1120) 1087.5,1126.5 1087.5,1334.5 1138.7,1385.7 1158.16,1385.7 1165.56,1378.3 1296.51,1378.3 1370.71,1452.5 1852.5,1452.5 1878,1478 2003.14,1478 2068,1413.14
  BOTTOM w4: v1(611,2087.5) 583.5,2115 560,2115 545,2100 545,2080 571,2054 571,1952 540,1921 540,1849 639,1750 813,1750 845.5,1717.5 845.5,1692.5 992,1546 1020,1546 1043.3,1522.7 1043.3,1473.3 948.8,1378.8 948.8,1267.76 1008.56,1208 1029.28,1208 1076,1161.28 1076,1138 v1(1094,1120) ; v1(1097,900) 1097.5,900.5 v1@1097.5,1120 ; v1(1201.8,429.54) 1233.74,429.54 1259.2,455 1283.4,455 1302.04,436.36 1385.36,436.36 1394,445 v1(1417,445) ; v1@2006,1038.08 v1(2009.8,1034.28) 2037.16,1061.63 2037.16,1119.08 2006,1150.24 2006,1246 2051.46,1291.46 v1(2064.86,1291.46) 2082.4,1309 R81.2@2121.31,1309 R81.2@2118.31,1312 ; v1(2177,902) 2197.5,881.5 2197.5,821.81 2179,803.31 R131.1@2179,792 2181.11,789.89 U4.21@2181.11,745.76
AR_SPICLK1: U2.E13 U14.7 | length 1760
  TOP w4: U14.7@1055.76,1260.13 1037.18,1260.13 1032.2,1255.15 1032.2,1249.88 1018,1235.68 1018,1200.69 1048.69,1170 1114,1170 1123,1179 1151,1179 v1(1163,1167) ; U2.E13@2166.87,1401.13 v1(2191,1377)
  TOP w5: U2.E13@2166.6,1401.13 U2.E13@2166.87,1401.13
  L3 w5: v1(1163,1167) 1213.7,1116.3 1213.7,1076.84 1194,1057.14 1194,982 1209,967 1791.49,967 2016.09,1191.6 2016.09,1235.2 2044.8,1263.9 2068.9,1263.9 2094.46,1289.46 2094.46,1298 2119.19,1322.73 2119.19,1387.22 2130.33,1398.36 2169.64,1398.36 v1(2191,1377)
AR_SYNC_IN: R62.2 R165.1 U2.P4 | length 3226.8
  TOP w4: R165.1@895,1599.01 929.57,1599.01 R62.2@929.85,1598.73 941.33,1598.73 946,1603.4 946,1678 952,1684 964,1684 968,1680 v1(968,1659) ; U2.P4@2396.91,1631.44 2410.2,1644.73 2410.2,1667.2 2442,1699 v1(2442,1718)
  L3 w5: v1(968,1659) 957,1648 957,1639 964,1632 982.14,1632 996.04,1645.9 1031.2,1645.9 1056.2,1670.9 1074.1,1670.9 1098.3,1646.7 1138.7,1646.7 1157.7,1665.7 1180.2,1665.7 1197.4,1648.5 1280.5,1648.5 1324.85,1604.15 1565.18,1604.15 1585.05,1584.28 1704.8,1584.28 1737,1616.48 1737,1655 1743,1661 1761,1661 1767,1655 1767,1627 1772,1622 1786,1622 1791,1627 1791,1653 1797,1659 1826.6,1659 1833.7,1651.9 1833.7,1624.95 1838.7,1619.95 1848.66,1619.95 1853.7,1624.99 1853.7,1650.8 1858.7,1655.8 1868.7,1655.8 1873.7,1650.8 1873.7,1631.41 1879.56,1625.55 1887.84,1625.55 1893.7,1631.41 1893.7,1650.4 1898.7,1655.4 1908.7,1655.4 1913.7,1650.4 1913.7,1631.41 1919.56,1625.55 1927.84,1625.55 1933.7,1631.41 1933.7,1675.7 1938,1680 1950,1680 1953.7,1676.3 1953.7,1602.3 1958,1598 1969.3,1598 1972.3,1601 1972.3,1692.3 1978,1698 1997,1698 2003,1692 2003,1641 2008,1636 2023,1636 2027,1640 2027,1690 2033,1696 2051,1696 2056,1691 2056,1657.1 2076.8,1636.3 2076.8,1601.23 2080.03,1598 2088,1598 2126,1636 2126,1720 2131,1725 2142,1725 2148,1719 2148,1657.99 2153.99,1652 2165,1652 2170,1657 2170,1706 2236.76,1772.76 2236.76,1826.24 2246.52,1836 2254.8,1836 2260.66,1830.14 2260.66,1776.66 2266.52,1770.8 2274.8,1770.8 2280.66,1776.66 2280.66,1830.14 2286.52,1836 2294.8,1836 2300.66,1830.14 2300.66,1776.66 2306.52,1770.8 2314.8,1770.8 2320.66,1776.66 2320.66,1830.14 2326.52,1836 2333.37,1836 2339.29,1830.08 2339.29,1753.71 2348,1745 2362,1745 2369,1752 2369,1774.45 2377.55,1783 2427,1783 2442,1768 v1(2442,1718)
AR_SYNC_OUT_SOP1: R108.2 R113.1 U2.G13 | length 2888.9
  TOP w4: R113.1@608.92,428.65 R113.1@608.92,427.86 608.92,409.08 615,403 675,403 683.91,411.91 1166.77,411.91 1169.39,409.29 1207.05,409.29 1309.84,512.07 R108.2@1330.35,512.07 1330.35,598.96 v1(1316.35,612.97)
  TOP w10: U2.G13@2166.6,1452.31 2166.69,1452.4 2167.09,1452 v1(2218,1452)
  L3 w5: v1(1236,1414) 1258.2,1391.8 1279.55,1391.8 1351.74,1464 1761,1464 1800.7,1503.7 2123.3,1503.7 2159,1468 2171.14,1468 2180.84,1458.3 2211.7,1458.3 v1(2218,1452)
  BOTTOM w4: v1(1236,1414) 1233,1414 1216.8,1397.8 1216.8,1332.96 1233.2,1316.56 1233.2,1257.76 1222.2,1246.76 1222.2,1142.48 1214,1134.28 1214,1076.73 1199.2,1061.93 1199.2,809.8 1297,712 1297,668.85 1296.3,668.15 1296.3,633.01 v1(1316.35,612.97)
AR_TCK: R66.2 R70.1 U2.P10 | length 1550.4
  TOP w4: R70.1@1091.33,1564.71 R70.1@1091.75,1565.13 R66.2@1091.75,1598.73 1102.73,1598.73 1107.02,1603.02 1107.02,1673.98 v1(1105,1676) ; v1(2192,1831) 2186,1825 2186,1734.6 2230.8,1689.8 2230.8,1644.04 2233.69,1641.15 2233.69,1641.05 2243.3,1631.44 U2.P10@2243.37,1631.44
  L3 w5: v1(1105,1676) 1287.6,1676 1320.12,1643.48 1707.3,1643.48 1806.83,1743 2140.46,1743 2192,1794.54 v1(2192,1831)
AR_TDI: R29.1 R30.1 U2.R11 | length 2154
  TOP w4: R29.1@963.83,2142.71 R30.1@995.75,2142.71 995.75,2167 995.75,2168.25 994.5,2167 v1(994,2167) ; v1(2167.14,1804.93) 2167.14,1741.14 2166,1740 2217.78,1688.22 U2.R11@2217.78,1657.03
  L3 w5: v1(979,1706) 998,1725 1132.14,1725 1147.6,1709.54 1277.06,1709.54 1297.77,1688.83 1672.27,1688.83 1736.44,1753 2114,1753 2165.93,1804.93 v1(2167.14,1804.93)
  BOTTOM w4: v1(979,1706) 979,1782 945,1816 928.35,1816 927.65,1815.3 873.55,1815.3 848.3,1840.55 848.3,1904.55 846.8,1906.05 846.8,1923.8 868.2,1945.2 868.2,2092.2 893,2117 971.23,2117 994,2139.77 v1(994,2167)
